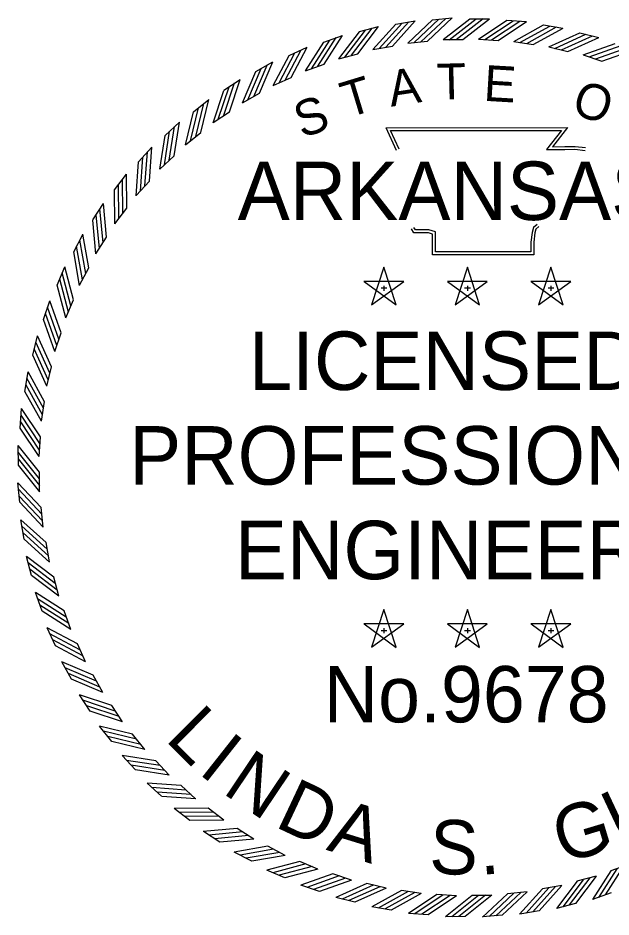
# Model space of a CAD drawing. Extents: x -43543 to 34500, y -13675 to 11152.
# Drawn here: x 9041 to 10683, y -8547 to -6059 of the extents above; entities that cross this region are included whole.
import ezdxf

# ---------------------------------------------------------------- set-up
doc = ezdxf.new("R2010")
doc.units = 0
doc.layers.add('STAMP', color=7, linetype='Continuous')

msp = doc.modelspace()

# ---------------------------------------------------------------- linework, layer by layer
at = {"layer": 'STAMP'}
for p, q in [((10087.2, -6076.7), (10140.8, -6067.3)), ((10189.1, -6064.5), (10243.4, -6059.5)), ((10292.3, -6061.5), (10346.8, -6061.5)), ((10394.4, -6065.6), (10448.7, -6069.6)), ((9986.5, -6097.3), (10039.2, -6083.4)), ((10496.2, -6078.8), (10550, -6087.3)), ((9887.9, -6126.1), (9939.3, -6107.9)), ((10218, -6119.5), (10272.6, -6119.5)), ((10316, -6118), (10370.4, -6122)), ((10596.6, -6100.4), (10649.6, -6113.3)), ((9792.1, -6162.9), (9841.8, -6140.6)), ((10024, -6146.7), (10077.8, -6137.3)), ((10120.4, -6129.1), (10174.8, -6124.1)), ((10413.8, -6124.5), (10467.7, -6133)), ((10510.7, -6139.1), (10563.7, -6152.1)), ((9929.4, -6172.3), (9982.2, -6158.4)), ((10606.1, -6161.7), (10657.9, -6179)), ((9699.6, -6207.6), (9747.2, -6181.2)), ((9837.2, -6205.5), (9888.7, -6187.3)), ((9611.1, -6259.7), (9656.4, -6229.5)), ((9748, -6246.3), (9797.8, -6223.9)), ((9662.6, -6294.3), (9710.4, -6267.9)), ((9527.2, -6319), (9569.9, -6285.1)), ((9581.4, -6349.2), (9626.8, -6318.9)), ((9448.5, -6384.9), (9488.2, -6347.7)), ((9505, -6410.6), (9547.7, -6376.6)), ((9375.5, -6457.2), (9412, -6416.8)), ((9433.9, -6478.1), (9473.7, -6440.7)), ((9308.7, -6535.2), (9341.8, -6491.9)), ((9368.6, -6551.2), (9405.3, -6510.7)), ((9248.6, -6618.5), (9278, -6572.6)), ((9309.6, -6629.5), (9342.8, -6586.1)), ((9195.6, -6706.5), (9221.1, -6658.3)), ((9257.3, -6712.4), (9286.8, -6666.4)), ((9150, -6798.5), (9171.4, -6748.4)), ((9212, -6799.3), (9237.6, -6751)), ((10054.2, -6749), (10020.1, -6853.5)), ((10088.2, -6853.5), (10054.3, -6748.8)), ((10285.3, -6749), (10251.2, -6853.5)), ((10319.3, -6853.5), (10285.4, -6748.8)), ((10516.4, -6749), (10482.4, -6853.5)), ((10550.4, -6853.5), (10516.5, -6748.8)), ((10109.2, -6788.9), (9999.2, -6788.8)), ((9999.3, -6788.9), (10088.2, -6853.6)), ((10020.3, -6853.5), (10109.3, -6788.9)), ((10340.3, -6788.9), (10230.3, -6788.8)), ((10230.4, -6788.9), (10319.3, -6853.6)), ((10251.4, -6853.5), (10340.4, -6788.9)), ((10571.4, -6788.9), (10461.4, -6788.8)), ((10461.5, -6788.9), (10550.4, -6853.6)), ((10482.5, -6853.5), (10571.5, -6788.9)), ((10046.4, -6806.5), (10062.7, -6806.5)), ((10054.3, -6800.6), (10054.3, -6814.4)), ((10277.5, -6806.5), (10293.8, -6806.5)), ((10285.4, -6800.6), (10285.4, -6814.4)), ((10508.6, -6806.5), (10525, -6806.5)), ((10516.5, -6800.6), (10516.5, -6814.4)), ((9174.1, -6889.7), (9195.5, -6839.5)), ((9112.2, -6894), (9129.4, -6842.3)), ((9082.4, -6992.3), (9095.2, -6939.3)), ((9143.7, -6982.9), (9160.9, -6931)), ((9060.8, -7092.7), (9069.2, -7038.9)), ((9121.1, -7078.2), (9134, -7025.2)), ((9047.5, -7194.5), (9051.5, -7140.2)), ((9106.5, -7175.2), (9115, -7121.2)), ((9099.9, -7272.9), (9103.9, -7218.5)), ((9042.8, -7297.1), (9042.3, -7242.7)), ((9101.4, -7371), (9100.9, -7316.3)), ((9046.5, -7399.8), (9041.5, -7345.5)), ((9111.1, -7468.5), (9106, -7414.1)), ((9058.7, -7501.8), (9049.2, -7448.1)), ((9128.7, -7564.9), (9119.2, -7511.1)), ((9079.2, -7602.4), (9065.4, -7549.7)), ((9154.2, -7659.5), (9140.3, -7606.7)), ((9108, -7701), (9089.9, -7649.6)), ((9187.5, -7751.7), (9169.3, -7700.3)), ((10054.2, -7696.6), (10020.1, -7801.1)), ((10088.2, -7801.1), (10054.3, -7696.4)), ((10285.3, -7696.6), (10251.2, -7801.1)), ((10319.3, -7801.1), (10285.4, -7696.4)), ((10516.4, -7696.6), (10482.4, -7801.1)), ((10550.4, -7801.1), (10516.5, -7696.4)), ((10109.2, -7736.5), (9999.2, -7736.4)), ((9999.3, -7736.5), (10088.2, -7801.2)), ((10020.3, -7801.1), (10109.3, -7736.5)), ((10340.3, -7736.5), (10230.3, -7736.4)), ((10230.4, -7736.5), (10319.3, -7801.2)), ((10251.4, -7801.1), (10340.4, -7736.5)), ((10571.4, -7736.5), (10461.4, -7736.4)), ((10461.5, -7736.5), (10550.4, -7801.2)), ((10482.5, -7801.1), (10571.5, -7736.5)), ((9144.9, -7796.8), (9122.5, -7747.1)), ((10046.4, -7754.1), (10062.7, -7754.1)), ((10054.3, -7748.2), (10054.3, -7762)), ((10277.5, -7754.1), (10293.8, -7754.1)), ((10285.4, -7748.2), (10285.4, -7762)), ((10508.6, -7754.1), (10525, -7754.1)), ((10516.5, -7748.2), (10516.5, -7762)), ((9228.3, -7840.9), (9205.9, -7791.1)), ((9189.5, -7889.3), (9163.2, -7841.7)), ((9276.3, -7926.3), (9249.8, -7878.6)), ((9241.7, -7977.8), (9211.4, -7932.5)), ((9331.1, -8007.6), (9300.8, -7962.1)), ((9300.9, -8061.7), (9267, -8019)), ((9392.5, -8084), (9358.6, -8041.2)), ((9366.9, -8140.4), (9329.6, -8100.7)), ((9460, -8155), (9422.7, -8115.2)), ((9439.1, -8213.4), (9398.7, -8176.9)), ((9533.2, -8220.3), (9492.7, -8183.7)), ((9517.2, -8280.2), (9473.9, -8247.1)), ((9611.5, -8279.3), (9568.1, -8246.1)), ((9694.3, -8331.6), (9648.3, -8302.1)), ((9600.5, -8340.3), (9554.6, -8310.9)), ((9781.3, -8376.9), (9733, -8351.3)), ((9688.4, -8393.3), (9640.3, -8367.9)), ((9871.6, -8414.9), (9821.4, -8393.4)), ((10733.7, -8401.4), (10682.2, -8419.6)), ((9780.5, -8438.9), (9730.4, -8417.5)), ((9964.8, -8445.2), (9913, -8428)), ((10060.2, -8467.8), (10007.1, -8454.9)), ((10641.5, -8434.7), (10588.7, -8448.6)), ((9875.9, -8476.7), (9824.3, -8459.5)), ((10157.1, -8482.4), (10103.2, -8473.9)), ((10450.5, -8477.9), (10396.1, -8482.9)), ((10546.9, -8460.2), (10493.1, -8469.7)), ((10682.9, -8480.9), (10631.6, -8499)), ((9974.2, -8506.6), (9921.3, -8493.7)), ((10254.9, -8489), (10200.4, -8485)), ((10352.9, -8487.5), (10298.3, -8488)), ((10074.6, -8528.1), (10020.8, -8519.7)), ((10483.7, -8530.2), (10430.1, -8539.7)), ((10584.3, -8509.7), (10531.6, -8523.5)), ((10176.5, -8541.4), (10122.2, -8537.4)), ((10279.1, -8546.1), (10224.6, -8546.6)), ((10381.7, -8542.4), (10327.5, -8547.4))]:
    msp.add_line(p, q, dxfattribs=at)
for points in [[(10059.8, -6140.2), (10122.9, -6070.2)], [(10077.7, -6137.2), (10140.9, -6067.2)], [(10120.4, -6129.2), (10189.1, -6064.6)], [(10137.8, -6127.7), (10206.5, -6063.1)], [(10156.6, -6125.6), (10225.3, -6061)], [(10174.7, -6124.1), (10243.4, -6059.5)], [(10217.9, -6119.5), (10292.2, -6061.6)], [(10235.4, -6119.7), (10309.8, -6061.7)], [(10254.4, -6119.3), (10328.7, -6061.3)], [(10272.5, -6119.4), (10346.8, -6061.5)], [(10315.9, -6118), (10394.3, -6065.6)], [(10333.4, -6119.4), (10411.8, -6067.1)], [(10352.3, -6120.4), (10430.7, -6068.1)], [(10370.4, -6121.9), (10448.8, -6069.6)], [(9946.3, -6168), (10003.5, -6093.1)], [(9964.5, -6162.8), (10021.7, -6087.8)], [(9982.1, -6158.4), (10039.3, -6083.4)], [(10023.9, -6146.8), (10087.1, -6076.8)], [(10041.2, -6143.9), (10104.4, -6073.9)], [(10413.7, -6124.6), (10496.1, -6078.8)], [(10431, -6127.4), (10513.4, -6081.7)], [(10449.7, -6130), (10532.2, -6084.3)], [(10467.6, -6133), (10550.1, -6087.3)], [(9871.4, -6193.2), (9922.2, -6113.8)], [(9888.6, -6187.3), (9939.3, -6107.9)], [(9929.3, -6172.3), (9986.5, -6097.4)], [(10510.6, -6139.2), (10596.5, -6100.4)], [(10527.6, -6143.5), (10613.5, -6104.7)], [(10546.1, -6147.6), (10632, -6108.8)], [(10563.7, -6152), (10649.6, -6113.3)], [(9797.8, -6223.9), (9841.8, -6140.5)], [(9837.1, -6205.6), (9887.9, -6126.2)], [(9853.7, -6199.9), (9904.5, -6120.5)], [(10606, -6161.8), (10694.8, -6130.2)], [(10622.6, -6167.4), (10711.4, -6135.9)], [(10640.7, -6173), (10729.5, -6141.5)], [(9748, -6246.4), (9792, -6163)], [(9764.1, -6239.3), (9808.1, -6156)], [(9781.1, -6231.2), (9825.2, -6147.8)], [(10657.8, -6178.9), (10746.7, -6147.4)], [(9694.3, -6276.5), (9731.3, -6189.8)], [(9710.3, -6267.9), (9747.3, -6181.1)], [(9662.5, -6294.4), (9699.5, -6207.7)], [(9678, -6286), (9714.9, -6199.3)], [(9611.5, -6328.8), (9641.2, -6239.3)], [(9626.7, -6318.9), (9656.4, -6229.4)], [(9581.3, -6349.3), (9611, -6259.8)], [(9596, -6339.7), (9625.7, -6250.2)], [(9547.7, -6376.7), (9569.9, -6285)], [(9504.9, -6410.7), (9527.2, -6319)], [(9518.8, -6399.9), (9541, -6308.3)], [(9533.3, -6387.8), (9555.6, -6296.2)], [(9460.3, -6453), (9474.9, -6359.9)], [(9473.7, -6440.7), (9488.2, -6347.6)], [(10089.3, -6426.2), (10060.3, -6363.3), (10562.8, -6363), (10520.8, -6415.7), (10554.9, -6415.3), (10583.4, -6414.9), (10611.9, -6418)], [(9433.9, -6478.2), (9448.4, -6385)], [(9446.8, -6466.3), (9461.3, -6373.1)], [(10096.5, -6422.8), (10072.7, -6371.2), (10546.3, -6370.9), (10504.1, -6423.9), (10555, -6423.2), (10583.1, -6422.9), (10611.1, -6425.9)], [(9405.2, -6510.7), (9412, -6416.7)], [(9392.9, -6524.1), (9399.7, -6430)], [(9368.6, -6551.3), (9375.5, -6457.3)], [(9380.5, -6538.4), (9387.3, -6444.4)], [(9342.7, -6586.1), (9341.8, -6491.9)], [(9331.6, -6600.4), (9330.6, -6506.2)], [(9309.6, -6629.6), (9308.7, -6535.3)], [(9320.4, -6615.7), (9319.5, -6521.5)], [(9276.8, -6681.6), (9268, -6587.7)], [(9286.7, -6666.4), (9278, -6572.6)], [(9266.9, -6697.8), (9258.2, -6603.9)], [(9257.3, -6712.5), (9248.6, -6618.6)], [(10483.6, -6636.7), (10475, -6643.7), (10472.2, -6654.1), (10469.3, -6680.2), (10469.3, -6714.9), (10188.8, -6714.9), (10188.8, -6668), (10188.8, -6657.6), (10177.4, -6654.1), (10137.5, -6654.1), (10130.4, -6643.3)], [(10478.6, -6630.6), (10468, -6639.2), (10464.3, -6652.7), (10461.4, -6679.8), (10461.4, -6707), (10196.8, -6707), (10196.8, -6668), (10196.8, -6651.7), (10178.6, -6646.2), (10141.8, -6646.2), (10137.1, -6639)], [(9237.5, -6751.1), (9221, -6658.2)], [(9220.4, -6784), (9203.9, -6691.1)], [(9228.9, -6767), (9212.4, -6674.2)], [(9212, -6799.4), (9195.6, -6706.6)], [(9188.2, -6856.1), (9164.1, -6765)], [(9195.5, -6839.5), (9171.4, -6748.3)], [(9181.1, -6873.7), (9157, -6782.5)], [(9174.1, -6889.7), (9150, -6798.6)], [(9155, -6948.3), (9123.5, -6859.4)], [(9160.9, -6931.1), (9129.4, -6842.2)], [(9149.4, -6966.3), (9117.9, -6877.5)], [(9143.7, -6982.9), (9112.2, -6894.1)], [(9134, -7025.2), (9095.2, -6939.3)], [(9129.5, -7042.8), (9090.8, -6956.9)], [(9125.4, -7061.3), (9086.7, -6975.4)], [(9121.1, -7078.3), (9082.4, -6992.4)], [(9114.9, -7121.3), (9069.2, -7038.8)], [(9111.9, -7139.2), (9066.2, -7056.7)], [(9109.4, -7157.9), (9063.7, -7075.5)], [(9106.5, -7175.2), (9060.8, -7092.8)], [(9103.9, -7218.5), (9051.5, -7140.1)], [(9102.4, -7236.6), (9050, -7158.2)], [(9101.4, -7255.5), (9049, -7177.1)], [(9100, -7273), (9047.6, -7194.6)], [(9100.9, -7316.4), (9042.2, -7242.6)], [(9100.9, -7334.6), (9042.2, -7260.8)], [(9101.5, -7353.5), (9042.8, -7279.7)], [(9101.5, -7371), (9042.8, -7297.2)], [(9106, -7414.2), (9041.5, -7345.5)], [(9107.5, -7432.3), (9043, -7363.6)], [(9109.7, -7451.1), (9045.1, -7382.4)], [(9111.1, -7468.6), (9046.6, -7399.8)], [(9119.2, -7511.2), (9049.2, -7448.1)], [(9122.2, -7529.1), (9052.2, -7466)], [(9125.9, -7547.7), (9055.9, -7484.5)], [(9128.8, -7565), (9058.7, -7501.8)], [(9140.3, -7606.8), (9065.3, -7549.7)], [(9144.8, -7624.4), (9069.8, -7567.2)], [(9150, -7642.6), (9075, -7585.4)], [(9154.3, -7659.6), (9079.3, -7602.4)], [(9169.3, -7700.3), (9089.8, -7649.6)], [(9175.2, -7717.5), (9095.7, -7666.7)], [(9181.9, -7735.2), (9102.4, -7684.4)], [(9187.6, -7751.8), (9108.1, -7701)], [(9205.9, -7791.1), (9122.5, -7747.1)], [(9213.1, -7807.8), (9129.8, -7763.7)], [(9221.3, -7824.9), (9137.9, -7780.8)], [(9228.3, -7840.9), (9145, -7796.9)], [(9249.8, -7878.6), (9163.1, -7841.6)], [(9258.5, -7894.6), (9171.7, -7857.6)], [(9268, -7911), (9181.3, -7874)], [(9276.3, -7926.4), (9189.6, -7889.4)], [(9300.8, -7962.2), (9211.4, -7932.5)], [(9310.8, -7977.4), (9221.3, -7947.7)], [(9321.6, -7992.9), (9232.1, -7963.2)], [(9331.2, -8007.6), (9241.7, -7977.9)], [(9358.6, -8041.2), (9267, -8019)], [(9369.8, -8055.6), (9278.1, -8033.4)], [(9381.8, -8070.1), (9290.2, -8047.9)], [(9392.6, -8084), (9301, -8061.8)], [(9422.7, -8115.3), (9329.6, -8100.7)], [(9435, -8128.6), (9341.8, -8114)], [(9448.2, -8142.1), (9355.1, -8127.6)], [(9460.1, -8155), (9367, -8140.5)], [(9492.7, -8183.7), (9398.7, -8176.9)], [(9506, -8196), (9412, -8189.2)], [(9520.4, -8208.4), (9426.3, -8201.6)], [(9533.3, -8220.3), (9439.2, -8213.5)], [(9568.1, -8246.2), (9473.8, -8247.1)], [(9582.4, -8257.3), (9488.1, -8258.3)], [(9597.7, -8268.5), (9503.4, -8269.5)], [(9611.5, -8279.3), (9517.3, -8280.2)], [(9648.4, -8302.2), (9554.5, -8310.9)], [(9663.6, -8312.1), (9569.7, -8320.9)], [(9679.7, -8322), (9585.9, -8330.7)], [(9694.4, -8331.6), (9600.5, -8340.3)], [(9733, -8351.4), (9640.2, -8367.9)], [(9749, -8360), (9656.2, -8376.5)], [(9765.9, -8368.5), (9673.1, -8385)], [(9781.3, -8376.9), (9688.5, -8393.3)], [(9821.4, -8393.4), (9730.3, -8417.5)], [(9838.1, -8400.7), (9746.9, -8424.8)], [(9855.6, -8407.8), (9764.5, -8431.9)], [(10717.2, -8407), (10666.4, -8486.5)], [(9871.7, -8414.8), (9780.5, -8438.9)], [(9913, -8428), (9824.2, -8459.6)], [(9930.2, -8433.9), (9841.4, -8465.4)], [(10682.3, -8419.6), (10631.5, -8499.1)], [(10699.4, -8413.7), (10648.7, -8493.2)], [(9948.3, -8439.5), (9859.4, -8471)], [(9964.9, -8445.2), (9876, -8476.7)], [(10007.2, -8454.9), (9921.2, -8493.7)], [(10588.8, -8448.6), (10531.6, -8523.6)], [(10606.3, -8444.1), (10549.2, -8519.1)], [(10624.5, -8438.9), (10567.4, -8513.9)], [(10641.5, -8434.6), (10584.4, -8509.6)], [(10024.8, -8459.4), (9938.8, -8498.1)], [(10043.3, -8463.5), (9957.3, -8502.2)], [(10060.3, -8467.8), (9974.3, -8506.5)], [(10103.2, -8474), (10020.8, -8519.7)], [(10121.1, -8477), (10038.7, -8522.7)], [(10139.9, -8479.5), (10057.4, -8525.2)], [(10157.2, -8482.4), (10074.7, -8528.1)], [(10396.1, -8482.9), (10327.4, -8547.5)], [(10414.2, -8481.4), (10345.5, -8546)], [(10433, -8479.3), (10364.3, -8543.8)], [(10450.5, -8477.8), (10381.8, -8542.4)], [(10493.2, -8469.7), (10430, -8539.7)], [(10511.1, -8466.7), (10447.9, -8536.8)], [(10529.6, -8463), (10466.5, -8533.1)], [(10546.9, -8460.2), (10483.8, -8530.2)], [(10200.5, -8485), (10122.1, -8537.4)], [(10218.6, -8486.5), (10140.2, -8538.9)], [(10237.5, -8487.5), (10159.1, -8539.9)], [(10255, -8489), (10176.6, -8541.3)], [(10298.4, -8488), (10224.6, -8546.7)], [(10316.5, -8488), (10242.7, -8546.7)], [(10335.4, -8487.4), (10261.6, -8546.1)], [(10353, -8487.4), (10279.2, -8546.1)]]:
    msp.add_lwpolyline(points, dxfattribs=at)

# ---------------------------------------------------------------- texts
for s, height, rotation, p in [('T', 99.1, 1.4789, (10202, -6285.5)), ('E', 99.1, 356.672, (10328.9, -6288.5)), ('T', 99.1, 16.9015, (9953.6, -6336.6)), ('A', 99.1, 8.6788, (10074, -6305.2)), ('O', 99.1, 341.2218, (10569.5, -6322.5)), ('S', 99.1, 19.7726, (9827.6, -6393.2)), ('L', 150.5, 315.1295, (9445.8, -8056.7)), ('I', 150.5, 321.696, (9537.3, -8147.8)), ('N', 150.5, 326.0736, (9603.9, -8202.5)), ('U', 150.5, 25.1712, (10706.4, -8350.7)), ('D', 150.5, 334.8288, (9748.6, -8295.8)), ('A', 150.5, 342.8544, (9892.3, -8361.1)), ('G', 150.5, 16.7808, (10549.2, -8400.8)), ('S', 150.5, 357.8112, (10178.4, -8426.9)), ('.', 150.5, 5.1072, (10321.8, -8431.4))]:
    msp.add_text(s, height=height, rotation=rotation, dxfattribs=at).set_placement(p)
for s, height, p in [('ARKANSAS', 161.78, (9649.5, -6618.7)), ('LICENSED', 161.78, (9680.3, -7088.9)), ('PROFESSIONAL', 161.779, (9349, -7350.8)), ('ENGINEER', 161.78, (9641.8, -7612.7)), ('No.9678', 156, (9887.6, -8008.8))]:
    msp.add_text(s, height=height, dxfattribs=at).set_placement(p)

doc.saveas('drawing.dxf')
